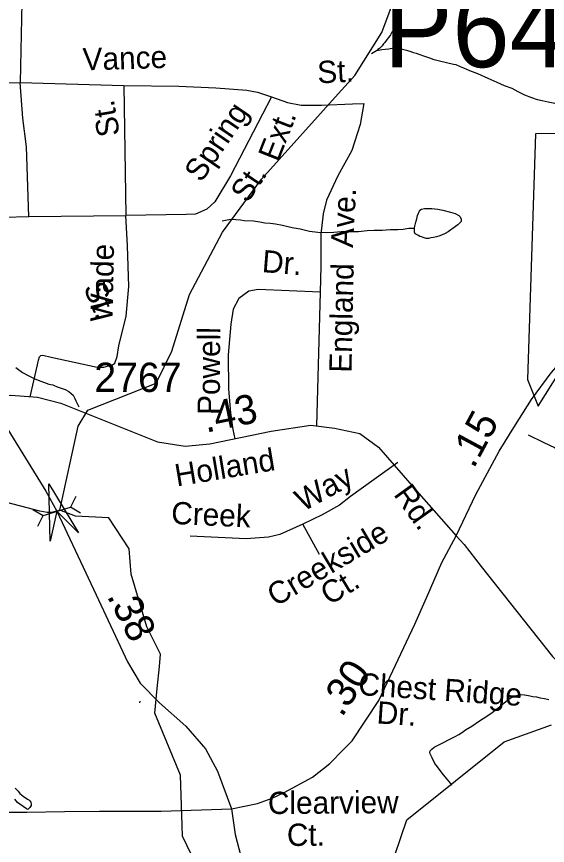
# Model space of a CAD drawing. Extents: x 2001466 to 2224147, y 644118 to 847247.
# Drawn here: x 2061459 to 2063724, y 663505 to 667039 of the extents above; entities that cross this region are included whole.
import ezdxf

# ---------------------------------------------------------------- set-up
doc = ezdxf.new("R2010")
doc.units = 0
for name, color, linetype in [('Exist Boundary Political City Limit New', 7, 'Continuous'), ('Exist Hydrographic Creek Single Shore', 7, 'Continuous'), ('Exist Hydrographic Misc Water Feature', 7, 'Continuous'), ('Exist Road Non-System Type 51', 7, 'Continuous'), ('Exist Road Non-System Type 51 Label', 7, 'Continuous'), ('Exist Road Secondary Mileage Hundredths English Label', 7, 'Continuous'), ('Exist Road Secondary Structure Pipe Attributed CELL', 7, 'Continuous'), ('Exist Road Secondary Structure Pipe CELL', 7, 'Continuous'), ('Exist Road Secondary Structure Pipe Number Label', 7, 'Continuous'), ('Exist Road Secondary Type 51 Attributed', 7, 'Continuous'), ('Exist Road Secondary Type 51 Label', 7, 'Continuous'), ('Exist Road Secondary Type 51 Number Label', 7, 'Continuous'), ('Map Preparation Boundary City Limit Buffer Line', 7, 'Continuous')]:
    doc.layers.add(name, color=color, linetype=linetype)

msp = doc.modelspace()

# ---------------------------------------------------------------- linework, layer by layer
at = {"layer": 'Exist Boundary Political City Limit New'}
msp.add_lwpolyline([(2064565.9, 666542.4), (2064486.8, 666543.2), (2063672.5, 666539.8), (2063639.6, 665492), (2063685.1, 665378.3), (2063834.6, 665615.3), (2063848.5, 665612), (2063857.8, 665626.4), (2063876.5, 665651.6), (2063956.1, 665744.4), (2064023, 665822.1), (2064123.5, 665937.9), (2064252.1, 666086.2), (2064367.1, 666218.8), (2064446.1, 666309.8), (2064504, 666385.2), (2064548.2, 666465.2), (2064534.6, 666467.1), (2064565.9, 666542.4)], dxfattribs=at)
at = {"layer": 'Exist Hydrographic Creek Single Shore'}
msp.add_lwpolyline([(2062528.2, 662520.3), (2062585.1, 662528.7), (2062671, 662713.7), (2062684.2, 662738.7), (2062703.3, 662758.5), (2062741.4, 662783.1), (2062787.6, 662812.8), (2062811, 662834.8), (2062829.4, 662864.8), (2062967.1, 663154.1), (2063124.2, 663613.5), (2063540.2, 663946.2), (2063741.9, 664019.3)], dxfattribs=at)
at = {"layer": 'Exist Hydrographic Misc Water Feature'}
msp.add_line((2062059.2, 664173.9), (2062068.2, 664268), dxfattribs=at)
for points in [[(2063080.3, 667214.7), (2063090.3, 667178.8), (2063094.4, 667146.8), (2063096.5, 667120.8), (2063094.6, 667100.8), (2063094.6, 667084.8), (2063092.6, 667066.8), (2063090.5, 667046.8), (2063086.8, 667024.8), (2063078.8, 667002.8), (2063070.6, 666988.8), (2063068.8, 666980.8), (2063060.8, 666972.8), (2063054.8, 666960.7), (2063046.8, 666950.7), (2063040.9, 666942.7), (2063030.9, 666928.7), (2063024.9, 666922.7), (2063018.8, 666914.7), (2063007.1, 666902.7), (2063000.9, 666898.7), (2062995, 666892.7)], [(2062831.5, 666709), (2062902.3, 666787.3), (2063018.1, 666971.9), (2063084.3, 667151.8)], [(2062995, 666892.7), (2062981, 666884.6), (2062973, 666880.6)], [(2063323.1, 666835.3), (2063263, 666849.2), (2063241, 666855.1), (2063223, 666861.1), (2063201, 666869.1), (2063177.1, 666877), (2063165, 666881), (2063153.1, 666884.9), (2063143, 666888.9), (2063129.1, 666892.9), (2063105.1, 666898.8), (2063085, 666900.8), (2063069, 666902.8), (2063061, 666902.8), (2063047.1, 666900.7), (2063031.1, 666898.7), (2063016.9, 666896.7), (2063003, 666894.7), (2062995, 666892.7)], [(2063899.3, 666648.4), (2063845.1, 666650.3), (2063821.1, 666654.3), (2063779.3, 666662.2), (2063755.3, 666668.1), (2063727.2, 666674), (2063701.2, 666680), (2063681.3, 666684), (2063657.3, 666691.9), (2063627.1, 666703.9), (2063599.1, 666717.8), (2063573, 666731.8), (2063541, 666743.7), (2063509, 666757.6), (2063471.1, 666775.5), (2063427, 666795.5), (2063393, 666807.4), (2063366.9, 666819.4), (2063353, 666825.4), (2063334.9, 666833.3), (2063323.1, 666835.3)], [(2061642.8, 664933.9), (2061722.2, 665292.2), (2061763.2, 665360.3), (2062055.2, 665475.8), (2062121.2, 665612.2), (2062196.3, 665853.5), (2062337.2, 666119.6), (2062503.3, 666345.9), (2062831.5, 666709)], [(2063156.3, 666137.1), (2063158.4, 666145.1), (2063162.3, 666163.1), (2063166.2, 666177.1), (2063170.3, 666191.1), (2063174.2, 666201.1), (2063176.2, 666207.1), (2063180.1, 666213.1), (2063186.1, 666217.2), (2063200, 666221.2), (2063216, 666221.2), (2063230.2, 666221.2), (2063244.1, 666219.2), (2063256, 666217.3), (2063278.1, 666213.3), (2063310.1, 666205.4), (2063330.2, 666199.4), (2063346.2, 666191.4), (2063352.2, 666185.5), (2063356.3, 666175.5), (2063356.3, 666165.5), (2063348.3, 666157.5), (2063342.1, 666151.4), (2063332.3, 666143.4), (2063320.2, 666135.4), (2063312.4, 666129.4), (2063300.3, 666121.4), (2063288.4, 666113.4), (2063272.4, 666107.4), (2063260.3, 666103.3), (2063250.3, 666099.3), (2063238.4, 666097.3), (2063226.3, 666095.2), (2063216.4, 666093.2), (2063206.4, 666093.2), (2063198.4, 666095.2), (2063186.3, 666099.2), (2063180.3, 666101.2), (2063174.4, 666105.2), (2063168.2, 666109.1), (2063160.2, 666113.1), (2063156.3, 666119.1), (2063156.3, 666131.1), (2063156.3, 666137.1)], [(2062336.5, 666167.6), (2062364.4, 666173.7), (2062378.4, 666175.7), (2062394.4, 666173.7), (2062414.3, 666171.7), (2062430.3, 666169.7), (2062470.2, 666167.8), (2062496.3, 666163.8), (2062518.4, 666159.9), (2062540.4, 666158), (2062564.4, 666156), (2062594.3, 666150), (2062634.5, 666140.1), (2062668.5, 666134.2), (2062708.5, 666124.3), (2062744.4, 666120.4), (2062782.5, 666118.4), (2062812.5, 666120.5), (2062844.3, 666122.6), (2062884.2, 666122.6), (2062918.3, 666122.7), (2062954.4, 666126.7), (2062984.3, 666128.8), (2063018.3, 666128.9), (2063052.4, 666130.9), (2063086.4, 666131), (2063108.4, 666133.1), (2063132.4, 666137.1), (2063156.3, 666137.1)], [(2061642.8, 664933.9), (2061630.4, 664929.5), (2061608.4, 664924.4), (2061590, 664924.4), (2061558.5, 664930.3), (2061248.5, 665011.7), (2060705.2, 665349), (2060046.3, 665605.2), (2059988.4, 665647.1)], [(2061455.6, 665542.1), (2061483.7, 665522.1), (2061507.7, 665508.1), (2061533.8, 665496.2), (2061557.8, 665486.3), (2061577.9, 665478.3), (2061595.9, 665472.3), (2061613.7, 665468.4), (2061631.8, 665460.4), (2061665.8, 665448.5), (2061681.8, 665440.5), (2061691.9, 665432.5), (2061699.9, 665424.5), (2061707.9, 665410.6), (2061712, 665400.6), (2061723.9, 665374.6)], [(2062068.2, 664268), (2062073.3, 664320.5), (2062015.2, 664436.5), (2061948.2, 664661.1), (2061939.2, 664769.5), (2061852.4, 664901.7), (2061710.2, 664908.3), (2061642.8, 664933.9)], [(2062164.8, 663589.2), (2062158.2, 663803.7), (2062049.1, 664068.4), (2062059.2, 664173.9)], [(2063316.7, 663760), (2063310.5, 663769.9), (2063296.6, 663787.9), (2063280.6, 663805.8), (2063266.5, 663823.8), (2063254.4, 663839.8), (2063244.3, 663853.8), (2063232.4, 663877.8), (2063224.4, 663895.7), (2063222.4, 663901.7), (2063224.4, 663907.7), (2063230.2, 663915.7), (2063240.2, 663923.7), (2063252.3, 663929.7), (2063278.4, 663941.8), (2063308.3, 663957.9), (2063330.2, 663969.9), (2063346.2, 663977.9), (2063362.2, 663987.9), (2063374.1, 663997.9), (2063402.2, 664014), (2063434, 664036.1), (2063450, 664046.2), (2063466, 664056.1), (2063488.1, 664072.2), (2063519.9, 664096.2), (2063539.8, 664112.2), (2063551.9, 664122.3), (2063565.8, 664132.3), (2063587.8, 664142.3), (2063609.7, 664148.4), (2063625.7, 664146.4), (2063643.8, 664144.4), (2063661.8, 664140.4), (2063677.8, 664138.5), (2063693.8, 664134.5), (2063711.8, 664130.6), (2063729.7, 664126.6)], [(2061453, 663748.4), (2061465.1, 663736.5), (2061473.1, 663726.5), (2061487, 663714.5), (2061505.1, 663702.5), (2061511, 663698.5), (2061515.1, 663694.5), (2061519.2, 663688.6), (2061521.1, 663680.6), (2061521.1, 663674.6), (2061515.1, 663666.6), (2061507.1, 663658.5), (2061501.2, 663660.5), (2061487.2, 663670.5), (2061473.1, 663680.4), (2061463.2, 663688.4), (2061450.9, 663702.4)], [(2062437.5, 662983), (2062166.2, 663544.3), (2062164.8, 663589.2)]]:
    msp.add_lwpolyline(points, dxfattribs=at)
at = {"layer": 'Exist Road Non-System Type 51'}
for p, q in [((2061481.3, 667099.6), (2061473.8, 666757.3)), ((2062753.8, 665863.6), (2062738.8, 665293.5)), ((2063641.7, 665256.3), (2063705.9, 665224.6)), ((2062751.6, 664745.6), (2062680.6, 664874.1)), ((2061985.1, 664113.1), (2061985.9, 664120))]:
    msp.add_line(p, q, dxfattribs=at)
for points in [[(2061115.7, 666749.3), (2061473.8, 666757.3)], [(2061511, 666186.1), (2061501.6, 666483), (2061485.6, 666606), (2061473.8, 666757.3)], [(2061473.8, 666757.3), (2061915.9, 666745)], [(2061915.9, 666745), (2061925.3, 666191.4)], [(2061915.9, 666745), (2062150.8, 666742.4), (2062308.5, 666735.7), (2062440.8, 666725), (2062487.6, 666717), (2062546.4, 666696.9)], [(2062546.4, 666696.9), (2062371.3, 666359.9), (2062304.5, 666248.9), (2062271.1, 666218.2), (2062223, 666196.8), (2062182.9, 666195.5), (2061925.3, 666191.4)], [(2062546.4, 666696.9), (2062614.8, 666673.1), (2062673.6, 666661.1), (2062760.5, 666661.1), (2062892.8, 666666.4), (2062940.9, 666669.1), (2062924.9, 666578.2), (2062888.8, 666468.5), (2062830, 666360.2), (2062781.9, 666256.7), (2062767.2, 666197.9), (2062757.8, 666111), (2062756.5, 665974.6), (2062753.8, 665863.6)], [(2061189.2, 666178.1), (2061511, 666186.1)], [(2061511, 666186.1), (2061925.3, 666191.4)], [(2061517.5, 665418.2), (2061547.6, 665554), (2061552, 665573.9), (2061556.3, 665587.8), (2061562.4, 665593.7), (2061570.4, 665595.5), (2061606.2, 665586.8), (2061803.4, 665544.8), (2061831.4, 665544.2), (2061851.5, 665549.8), (2061863.5, 665551.6), (2061877.7, 665561.3), (2061888.3, 665589.1), (2061895.2, 665634.9), (2061927.1, 665762.2), (2061937.8, 665887.9), (2061932.5, 666061.7), (2061925.3, 666191.4)], [(2062753.8, 665863.6), (2062489.2, 665874.8), (2062450.5, 665868.1), (2062407.7, 665837.4), (2062383.6, 665791.9), (2062372.9, 665727.7), (2062362.3, 665596.7), (2062363.6, 665450.9), (2062371.6, 665349.3), (2062381, 665278.4), (2062389.5, 665239.1)], [(2063705.9, 665224.6), (2063709.1, 665223), (2063754.6, 665202), (2063784.2, 665181.4), (2063805.8, 665159), (2063825.2, 665132.6), (2063838.7, 665104.3), (2063850, 665074.1), (2063861.3, 665035.9), (2063874.6, 665005.6), (2063888.4, 664991.3), (2063914, 664972.8), (2063957.6, 664953.9), (2064001.2, 664935), (2064036.8, 664916.3), (2064056.7, 664907.9), (2064262, 664875.7), (2064315.9, 664872.6), (2064344, 664874.1), (2064379.9, 664873.4), (2064416.1, 664878.6), (2064442.1, 664880.1), (2064474, 664877.4), (2064488.2, 664876.4)], [(2063085.5, 665137.8), (2062884, 664992.3), (2062836.2, 664955.5), (2062762.6, 664915), (2062680.6, 664874.1)], [(2062680.6, 664874.1), (2062582.3, 664830.3), (2062534.5, 664819.3), (2062438.8, 664811.9), (2062199.6, 664823)]]:
    msp.add_lwpolyline(points, dxfattribs=at)
at = {"layer": 'Exist Road Secondary Structure Pipe Attributed CELL'}
msp.add_lwpolyline([(2061601.7, 664802.8), (2061596.1, 665046.5), (2061722.9, 664838.3), (2061630.4, 664929.5)], close=True, dxfattribs=at)
at = {"layer": 'Exist Road Secondary Structure Pipe CELL'}
for p, q in [((2061711.1, 664992.3), (2061688.3, 664947)), ((2061572.5, 664912.1), (2061688.3, 664947)), ((2061732.3, 664921.7), (2061688.3, 664947)), ((2061528.4, 664937.4), (2061572.5, 664912.1)), ((2061549.6, 664866.8), (2061572.5, 664912.1))]:
    msp.add_line(p, q, dxfattribs=at)
at = {"layer": 'Exist Road Secondary Type 51 Attributed'}
for points in [[(2063334.7, 664824.4), (2063418, 665001.2), (2063517.8, 665186.1), (2063587.3, 665297.8), (2063656.7, 665406.2), (2063739.8, 665519.6), (2063801.3, 665590.2), (2063911, 665731.7), (2064299.1, 666160.9), (2064474.2, 666376.1), (2064537.6, 666479.6), (2064569.5, 666562.2), (2064586.6, 666617), (2064605.1, 666682.5), (2064613.5, 666738.3), (2064638.2, 666937.1), (2064668.7, 667269), (2064684.5, 667488.4)], [(2061300.2, 665421.2), (2061434.2, 665424.3), (2061548.2, 665415.9), (2061647.4, 665390.5), (2062059.6, 665225.8), (2062178.9, 665207.8), (2062283.4, 665217.3), (2062545.7, 665271.2), (2062714.6, 665296.5), (2062815.9, 665283.8), (2062923.6, 665260.6), (2063003.8, 665203.6), (2063174.8, 665005), (2063334.7, 664824.4)], [(2061300.2, 665421.2), (2061421.5, 665278.6), (2061583.4, 665015.4), (2061630.4, 664929.5), (2061798.2, 664573.1), (2061931.9, 664287.8), (2061986.8, 664196.9), (2062069.1, 664112.4), (2062181, 664013.1), (2062264.4, 663916), (2062316.1, 663822), (2062375.7, 663661.3)], [(2062375.7, 663661.3), (2062486.9, 663683.4), (2062549.1, 663706.3), (2062601.4, 663730.2), (2062721.9, 663796.4), (2062795.6, 663854.8), (2062854, 663913.2), (2062891.2, 663951.4), (2063005.2, 664122.1), (2063157.6, 664448), (2063208.4, 664561), (2063273.9, 664711.5), (2063334.7, 664824.4)], [(2063334.7, 664824.4), (2063369.2, 664787.7), (2063441.6, 664693.7), (2063745.8, 664311), (2063802.8, 664255), (2063875.7, 664217), (2063981.2, 664165.3), (2064049.8, 664114.6), (2064173.9, 663955.1), (2064440.4, 663610.7), (2064556.5, 663481.8)], [(2059295.4, 663712.5), (2059655.5, 663648.6), (2059810.2, 663627.6), (2059957.1, 663625), (2060124.9, 663627.6), (2060221.5, 663629.9), (2060288.5, 663629.9), (2060350.5, 663631.9), (2060398.5, 663632.9), (2060584.6, 663636), (2060793.7, 663639), (2060842.9, 663638), (2060893.9, 663639), (2060999.9, 663639), (2061124.9, 663643), (2061238, 663645.1), (2061313, 663646.1), (2061400.1, 663646.1), (2061503.1, 663647.1), (2061663.2, 663650.1), (2061812.2, 663651.1), (2062075.5, 663651.2), (2062375.7, 663661.3)], [(2062375.7, 663661.3), (2062391.1, 663551.5), (2062447.5, 663340.1), (2062501.7, 663203.7), (2062684.2, 662880.7), (2062741.4, 662783.1)]]:
    msp.add_lwpolyline(points, dxfattribs=at)
at = {"layer": 'Map Preparation Boundary City Limit Buffer Line'}
msp.add_lwpolyline([(2064565.9, 666542.4), (2064486.8, 666543.2), (2063672.5, 666539.8), (2063639.6, 665492), (2063685.1, 665378.3), (2063834.6, 665615.3), (2063848.5, 665612), (2063857.8, 665626.4), (2063876.5, 665651.6), (2063956.1, 665744.4), (2064023, 665822.1), (2064123.5, 665937.9), (2064252.1, 666086.2), (2064367.1, 666218.8), (2064446.1, 666309.8), (2064504, 666385.2), (2064548.2, 666465.2), (2064534.6, 666467.1), (2064565.9, 666542.4)], dxfattribs=at)

# ---------------------------------------------------------------- texts
at = {"layer": 'Exist Road Non-System Type 51 Label'}
for s, rotation, p in [('Vance', 1.7541, (2061742.2, 666809.3)), (' St.', 2.8924, (2062709.2, 666752.1)), (' St.', 99.728, (2061905.6, 666500.7)), ('Spring', 55.7568, (2062246.8, 666327.7)), ('Ext.', 68.5559, (2062575.1, 666415.6)), ('St.', 55.7568, (2062443.9, 666240.4)), ('Ave.', 86.7459, (2062893.8, 666052.3)), ('Wade', 88.8344, (2061868.1, 665737.4)), ('Dr.', 355.3627, (2062503.7, 665949.7)), ('England', 88.807, (2062888, 665520)), (' St.', 292.7956, (2061729.2, 665916.9)), ('Powell', 89.6802, (2062325.9, 665340.2)), ('Way', 28.8254, (2062681.3, 664926.4)), ('Creek', 357.3559, (2062117.3, 664876)), ('Creekside', 30.7199, (2062564.4, 664520.8)), ('Ct.', 31.2092, (2062792.9, 664526.3)), ('Chest Ridge', 356.1113, (2062914.9, 664146.5)), ('Dr.', 356.1113, (2062993.4, 664025.3)), ('Clearview', 0.4195, (2062531.7, 663638.4)), ('Ct.', 0.4195, (2062612.7, 663502.4))]:
    msp.add_text(s, height=95, rotation=rotation, dxfattribs=at).set_placement(p)
at = {"layer": 'Exist Road Secondary Mileage Hundredths English Label'}
for s, rotation, p in [('.43', 11.6057, (2062267, 665264.2)), ('.15', 61.6362, (2063409.3, 665107.9)), ('.38', 297.2715, (2061842.6, 664568.4)), ('.30', 56.2669, (2062846.6, 664047.8))]:
    msp.add_text(s, height=125, rotation=rotation, dxfattribs=at).set_placement(p)
at = {"layer": 'Exist Road Secondary Structure Pipe Number Label'}
msp.add_text('P642', height=328.08, dxfattribs=at).set_placement((2063026.2, 666823.2))
at = {"layer": 'Exist Road Secondary Type 51 Label'}
for s, rotation, p in [('Holland', 9.466, (2062142.4, 665035.1)), ('Rd.', 305.5269, (2063064.8, 665001.3))]:
    msp.add_text(s, height=95, rotation=rotation, dxfattribs=at).set_placement(p)
at = {"layer": 'Exist Road Secondary Type 51 Number Label'}
msp.add_text('2767', height=125, dxfattribs=at).set_placement((2061790.7, 665438.4))

doc.saveas('drawing.dxf')
